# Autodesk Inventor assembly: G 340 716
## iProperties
Created: 2005-06
Part Number: G 340 716
Document SubType Name: Assembly
Designer: I.Baliuc
Manufacturer: Standard
Standards Organization: Custom
Description: Kontaktplatte
Mass: 724.653 g
Surface Area: 161.469 cm^2
Volume: 80.87 cm^3
Density: 8.96072 g/cm^3
Title: Kontaktplatte
Company: Mayer & Müller AG Schaltgeräte
Author: T.Messerschmitt
Revision Number: 340716
